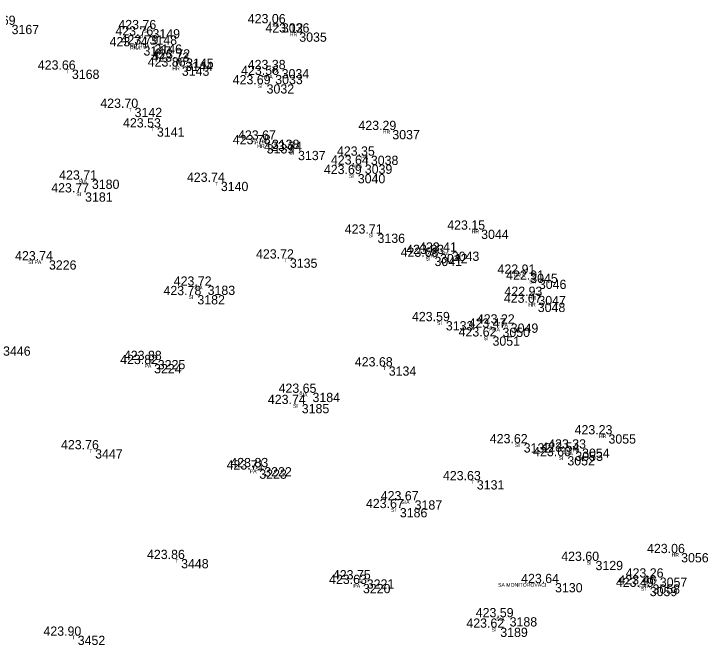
# Model space of a CAD drawing. Extents: x -639390 to -639075, y -1138747 to -1138358.
# Drawn here: x -639201.5 to -639145.2, y -1138568.4 to -1138517.2 of the extents above; entities that cross this region are included whole.
import ezdxf

# ---------------------------------------------------------------- set-up
doc = ezdxf.new("R2010")
doc.units = 0
for name, color, linetype in [('Vrstva 11', 7, 'Continuous'), ('Vrstva 12', 7, 'Continuous'), ('Vrstva 13', 7, 'Continuous'), ('Vrstva 57', 7, 'Continuous')]:
    doc.layers.add(name, color=color, linetype=linetype)

msp = doc.modelspace()

# ---------------------------------------------------------------- linework, layer by layer
at = {"layer": 'Vrstva 11'}
for p, q in [((-639180.04, -1138517.92), (-639180.04, -1138517.92)), ((-639190.53, -1138518.4), (-639190.53, -1138518.4)), ((-639178.63, -1138518.67), (-639178.63, -1138518.67)), ((-639190.77, -1138518.91), (-639190.77, -1138518.91)), ((-639191.26, -1138519.79), (-639191.26, -1138519.79)), ((-639190.37, -1138519.64), (-639190.37, -1138519.64)), ((-639187.8, -1138520.78), (-639187.8, -1138520.78)), ((-639188.15, -1138521.43), (-639188.15, -1138521.43)), ((-639187.87, -1138521.04), (-639187.87, -1138521.04)), ((-639197.06, -1138521.68), (-639197.06, -1138521.68)), ((-639180.06, -1138521.64), (-639180.06, -1138521.64)), ((-639180.58, -1138522.11), (-639180.58, -1138522.11)), ((-639181.28, -1138522.87), (-639181.28, -1138522.87)), ((-639191.98, -1138524.78), (-639191.98, -1138524.78)), ((-639190.17, -1138526.37), (-639190.17, -1138526.37)), ((-639171.09, -1138526.58), (-639171.09, -1138526.58)), ((-639180.85, -1138527.36), (-639180.85, -1138527.36)), ((-639181.27, -1138527.73), (-639181.27, -1138527.73)), ((-639178.73, -1138528.27), (-639178.73, -1138528.27)), ((-639172.83, -1138528.66), (-639172.83, -1138528.66)), ((-639173.32, -1138529.38), (-639173.32, -1138529.38)), ((-639173.89, -1138530.15), (-639173.89, -1138530.15)), ((-639195.44, -1138530.6), (-639195.44, -1138530.6)), ((-639184.99, -1138530.78), (-639184.99, -1138530.78)), ((-639195.99, -1138531.64), (-639195.99, -1138531.64)), ((-639172.29, -1138534.98), (-639172.29, -1138534.98)), ((-639163.89, -1138534.66), (-639163.89, -1138534.66)), ((-639167.22, -1138536.63), (-639167.22, -1138536.63)), ((-639166.27, -1138536.44), (-639166.27, -1138536.44)), ((-639198.92, -1138537.15), (-639198.92, -1138537.15)), ((-639179.39, -1138537), (-639179.39, -1138537)), ((-639167.67, -1138536.86), (-639167.67, -1138536.86)), ((-639159.91, -1138538.23), (-639159.91, -1138538.23)), ((-639159.21, -1138538.72), (-639159.21, -1138538.72)), ((-639186.06, -1138539.2), (-639186.06, -1138539.2)), ((-639186.89, -1138539.97), (-639186.89, -1138539.97)), ((-639159.25, -1138540.03), (-639159.25, -1138540.03)), ((-639159.3, -1138540.59), (-639159.3, -1138540.59)), ((-639166.75, -1138542.08), (-639166.75, -1138542.08)), ((-639161.49, -1138542.27), (-639161.49, -1138542.27)), ((-639162.16, -1138542.61), (-639162.16, -1138542.61)), ((-639162.97, -1138543.32), (-639162.97, -1138543.32)), ((-639190.4, -1138545.56), (-639190.4, -1138545.56)), ((-639190.1, -1138545.23), (-639190.1, -1138545.23)), ((-639171.38, -1138545.75), (-639171.38, -1138545.75)), ((-639177.56, -1138547.89), (-639177.56, -1138547.89)), ((-639178.43, -1138548.8), (-639178.43, -1138548.8)), ((-639153.57, -1138551.26), (-639153.57, -1138551.26)), ((-639195.18, -1138552.47), (-639195.18, -1138552.47)), ((-639160.44, -1138551.98), (-639160.44, -1138551.98)), ((-639155.71, -1138552.41), (-639155.71, -1138552.41)), ((-639156.9, -1138553.03), (-639156.9, -1138553.03)), ((-639156.25, -1138552.66), (-639156.25, -1138552.66)), ((-639181.87, -1138554.11), (-639181.87, -1138554.11)), ((-639181.47, -1138553.92), (-639181.47, -1138553.92)), ((-639164.24, -1138554.98), (-639164.24, -1138554.98)), ((-639169.28, -1138556.61), (-639169.28, -1138556.61)), ((-639170.48, -1138557.24), (-639170.48, -1138557.24)), ((-639147.68, -1138560.89), (-639147.68, -1138560.89)), ((-639188.21, -1138561.37), (-639188.21, -1138561.37)), ((-639154.62, -1138561.52), (-639154.62, -1138561.52)), ((-639173.16, -1138563.02), (-639173.16, -1138563.02)), ((-639149.41, -1138562.87), (-639149.41, -1138562.87)), ((-639173.47, -1138563.39), (-639173.47, -1138563.39)), ((-639157.9, -1138563.32), (-639157.9, -1138563.32)), ((-639150.22, -1138563.63), (-639150.22, -1138563.63)), ((-639150, -1138563.43), (-639150, -1138563.43)), ((-639161.58, -1138566.09), (-639161.58, -1138566.09)), ((-639162.34, -1138566.94), (-639162.34, -1138566.94)), ((-639196.59, -1138567.59), (-639196.59, -1138567.59))]:
    msp.add_line(p, q, dxfattribs=at)

# ---------------------------------------------------------------- texts
at = {"layer": 'Vrstva 12'}
for s, p in [('423.69 ', (-639204.419, -1138518.05)), ('423.06 ', (-639182.526, -1138517.92)), ('423.76 ', (-639193.256, -1138518.91)), ('423.76 ', (-639193.016, -1138518.4)), ('423.12 ', (-639181.099, -1138518.67)), ('423.74 ', (-639193.729, -1138519.79)), ('423.79 ', (-639192.839, -1138519.64)), ('423.73 ', (-639190.339, -1138521.04)), ('423.72 ', (-639190.269, -1138520.78)), ('423.66 ', (-639199.546, -1138521.68)), ('423.86 ', (-639190.636, -1138521.43)), ('423.38 ', (-639182.529, -1138521.64)), ('423.56 ', (-639183.066, -1138522.11)), ('423.69 ', (-639183.749, -1138522.87)), ('423.70 ', (-639194.479, -1138524.78)), ('423.53 ', (-639192.639, -1138526.37)), ('423.29 ', (-639173.559, -1138526.58)), ('423.78 ', (-639183.739, -1138527.73)), ('423.67 ', (-639183.319, -1138527.36)), ('423.74 ', (-639181.199, -1138528.27)), ('423.35 ', (-639175.3, -1138528.66)), ('423.64 ', (-639175.789, -1138529.38)), ('423.69 ', (-639176.359, -1138530.15)), ('423.71 ', (-639197.815, -1138530.6)), ('423.74 ', (-639187.459, -1138530.78)), ('423.77 ', (-639198.459, -1138531.64)), ('423.15 ', (-639166.36, -1138534.66)), ('423.71 ', (-639174.665, -1138534.98)), ('423.68 ', (-639170.139, -1138536.86)), ('423.63 ', (-639169.689, -1138536.63)), ('423.41 ', (-639168.645, -1138536.44)), ('423.74 ', (-639201.389, -1138537.15)), ('423.72 ', (-639181.859, -1138537)), ('422.91 ', (-639162.285, -1138538.23)), ('422.91 ', (-639161.585, -1138538.72)), ('423.72 ', (-639188.529, -1138539.2)), ('423.78 ', (-639189.359, -1138539.97)), ('422.93 ', (-639161.719, -1138540.03)), ('423.07 ', (-639161.769, -1138540.59)), ('423.59 ', (-639169.219, -1138542.08)), ('423.22 ', (-639163.959, -1138542.27)), ('423.47 ', (-639164.629, -1138542.61)), ('423.62 ', (-639165.439, -1138543.32)), ('423.88 ', (-639192.569, -1138545.23)), ('423.82 ', (-639192.869, -1138545.56)), ('423.68 ', (-639173.849, -1138545.75)), ('423.65 ', (-639180.03, -1138547.89)), ('423.74 ', (-639180.899, -1138548.8)), ('423.23 ', (-639156.039, -1138551.26)), ('423.62 ', (-639162.909, -1138551.98)), ('423.76 ', (-639197.666, -1138552.47)), ('423.54 ', (-639158.719, -1138552.66)), ('423.33 ', (-639158.179, -1138552.41)), ('423.60 ', (-639159.399, -1138553.03)), ('423.71 ', (-639184.245, -1138554.11)), ('423.83 ', (-639183.939, -1138553.92)), ('423.63 ', (-639166.709, -1138554.98)), ('423.67 ', (-639171.749, -1138556.61)), ('423.67 ', (-639172.949, -1138557.24)), ('423.06 ', (-639150.166, -1138560.89)), ('423.86 ', (-639190.696, -1138561.37)), ('423.60 ', (-639157.119, -1138561.52)), ('423.75 ', (-639175.63, -1138563.02)), ('423.64 ', (-639160.369, -1138563.32)), ('423.26 ', (-639151.896, -1138562.87)), ('423.63 ', (-639175.939, -1138563.39)), ('423.49 ', (-639152.689, -1138563.63)), ('423.46 ', (-639152.486, -1138563.43)), ('423.59 ', (-639164.049, -1138566.09)), ('423.62 ', (-639164.809, -1138566.94)), ('423.90 ', (-639199.089, -1138567.59))]:
    msp.add_text(s, height=0.75, dxfattribs=at).set_placement(p)
at = {"layer": 'Vrstva 13'}
for s, p in [(' 3167', (-639201.95, -1138518.8)), (' 3036', (-639180.04, -1138518.67)), (' 3149', (-639190.53, -1138519.15)), (' 3035', (-639178.63, -1138519.42)), (' 3148', (-639190.77, -1138519.66)), (' 3147', (-639191.26, -1138520.54)), (' 3146', (-639190.37, -1138520.39)), (' 3145', (-639187.8, -1138521.53)), (' 3143', (-639188.15, -1138522.18)), (' 3144', (-639187.87, -1138521.79)), (' 3168', (-639197.06, -1138522.43)), (' 3034', (-639180.06, -1138522.39)), (' 3033', (-639180.58, -1138522.86)), (' 3032', (-639181.28, -1138523.62)), (' 3142', (-639191.98, -1138525.53)), (' 3141', (-639190.17, -1138527.12)), (' 3037', (-639171.09, -1138527.33)), (' 3139', (-639181.27, -1138528.48)), (' 3138', (-639180.85, -1138528.11)), (' 3137', (-639178.73, -1138529.02)), (' 3038', (-639172.83, -1138529.41)), (' 3039', (-639173.32, -1138530.13)), (' 3040', (-639173.89, -1138530.9)), (' 3180', (-639195.44, -1138531.35)), (' 3140', (-639184.99, -1138531.53)), (' 3181', (-639195.99, -1138532.39)), (' 3136', (-639172.29, -1138535.73)), (' 3044', (-639163.89, -1138535.41)), (' 3042', (-639167.22, -1138537.38)), (' 3043', (-639166.27, -1138537.19)), (' 3226', (-639198.92, -1138537.9)), (' 3135', (-639179.39, -1138537.75)), (' 3041', (-639167.67, -1138537.61)), (' 3045', (-639159.91, -1138538.98)), (' 3046', (-639159.21, -1138539.47)), (' 3183', (-639186.06, -1138539.95)), (' 3182', (-639186.89, -1138540.72)), (' 3047', (-639159.25, -1138540.78)), (' 3048', (-639159.3, -1138541.34)), (' 3133', (-639166.75, -1138542.83)), (' 3049', (-639161.49, -1138543.02)), (' 3050', (-639162.16, -1138543.36)), (' 3051', (-639162.97, -1138544.07)), (' 3446', (-639202.64, -1138544.88)), (' 3224', (-639190.4, -1138546.31)), (' 3225', (-639190.1, -1138545.98)), (' 3134', (-639171.38, -1138546.5)), (' 3184', (-639177.56, -1138548.64)), (' 3185', (-639178.43, -1138549.55)), (' 3055', (-639153.57, -1138552.01)), (' 3447', (-639195.18, -1138553.22)), (' 3132', (-639160.44, -1138552.73)), (' 3054', (-639155.71, -1138553.16)), (' 3052', (-639156.9, -1138553.78)), (' 3053', (-639156.25, -1138553.41)), (' 3223', (-639181.87, -1138554.86)), (' 3222', (-639181.47, -1138554.67)), (' 3131', (-639164.24, -1138555.73)), (' 3187', (-639169.28, -1138557.36)), (' 3186', (-639170.48, -1138557.99)), (' 3056', (-639147.68, -1138561.64)), (' 3448', (-639188.21, -1138562.12)), (' 3129', (-639154.62, -1138562.27)), (' 3221', (-639173.16, -1138563.77)), (' 3057', (-639149.41, -1138563.62)), (' 3220', (-639173.47, -1138564.14)), (' 3130', (-639157.9, -1138564.07)), (' 3059', (-639150.22, -1138564.38)), (' 3058', (-639150, -1138564.18)), (' 3188', (-639161.58, -1138566.84)), (' 3189', (-639162.34, -1138567.69)), (' 3452', (-639196.59, -1138568.34))]:
    msp.add_text(s, height=0.75, dxfattribs=at).set_placement(p)
at = {"layer": 'Vrstva 57'}
for s, p in [('SA', (-639180.54, -1138518.22)), ('SI', (-639190.968, -1138518.7)), ('HR', (-639179.119, -1138518.97)), ('PA', (-639191.27, -1138519.21)), ('HR HRA', (-639192.07, -1138519.94)), ('PAA', (-639192.06, -1138520.09)), ('SI', (-639188.238, -1138521.08)), ('HR', (-639188.639, -1138521.73)), ('PA', (-639188.37, -1138521.34)), ('T', (-639197.26, -1138521.98)), ('PA', (-639180.56, -1138521.94)), ('HRA', (-639181.38, -1138522.41)), ('SI', (-639181.718, -1138523.17)), ('T', (-639192.18, -1138525.08)), ('T', (-639190.37, -1138526.67)), ('HR', (-639171.579, -1138526.88)), ('PA HR', (-639182.239, -1138527.66)), ('HR', (-639181.759, -1138528.03)), ('SI', (-639179.168, -1138528.57)), ('PA', (-639173.33, -1138528.96)), ('HRA', (-639174.12, -1138529.68)), ('SI', (-639174.328, -1138530.45)), ('SIA', (-639196.24, -1138530.9)), ('T', (-639185.19, -1138531.08)), ('SI', (-639196.428, -1138531.94)), ('SI', (-639172.728, -1138535.28)), ('HR', (-639164.379, -1138534.96)), ('HRA', (-639168.02, -1138536.93)), ('PA', (-639166.77, -1138536.74)), ('SI PA', (-639200.32, -1138537.45)), ('T', (-639179.59, -1138537.3)), ('SI', (-639168.108, -1138537.16)), ('HR K', (-639160.985, -1138538.53)), ('SA', (-639159.71, -1138539.02)), ('SIA', (-639186.86, -1138539.5)), ('SI', (-639187.328, -1138540.27)), ('HR', (-639159.739, -1138540.33)), ('HR', (-639159.789, -1138540.89)), ('SI', (-639167.188, -1138542.38)), ('PA', (-639161.99, -1138542.57)), ('HRA', (-639162.96, -1138542.91)), ('SI', (-639163.408, -1138543.62)), ('PA', (-639190.9, -1138545.86)), ('SI', (-639190.538, -1138545.53)), ('T', (-639171.58, -1138546.05)), ('SIA', (-639178.36, -1138548.19)), ('SI', (-639178.868, -1138549.1)), ('HR', (-639154.059, -1138551.56)), ('T', (-639195.38, -1138552.77)), ('SI', (-639160.878, -1138552.28)), ('PA', (-639156.21, -1138552.71)), ('SI', (-639157.338, -1138553.33)), ('HRA', (-639157.05, -1138552.96)), ('PA', (-639182.37, -1138554.41)), ('SI', (-639181.908, -1138554.22)), ('T', (-639164.44, -1138555.28)), ('SIA', (-639170.08, -1138556.91)), ('SI', (-639170.918, -1138557.54)), ('HR', (-639148.169, -1138561.19)), ('T', (-639188.41, -1138561.67)), ('SI', (-639155.058, -1138561.82)), ('SI', (-639173.598, -1138563.32)), ('PA', (-639149.91, -1138563.17)), ('PA', (-639173.97, -1138563.69)), ('SA MONITOROVACI', (-639162.238, -1138563.62)), ('HRA', (-639150.8, -1138563.73)), ('SI', (-639150.658, -1138563.93)), ('SIA', (-639162.38, -1138566.39)), ('SI', (-639162.778, -1138567.24)), ('T', (-639196.79, -1138567.89))]:
    msp.add_text(s, height=0.3, dxfattribs=at).set_placement(p)

doc.saveas('drawing.dxf')
